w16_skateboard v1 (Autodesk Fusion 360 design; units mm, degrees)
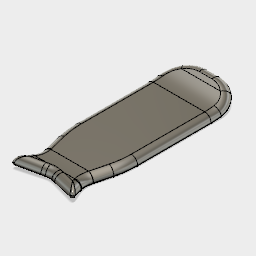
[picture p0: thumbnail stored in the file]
sketch "Sketch1" plane through (0, 0, 0) normal (1, 0, 0) x axis (0, 0, -1)
  line L1 (0, 0) -> (-50, 8.8163)
  line L2 (300, 0) -> (0, 0)
  line L3 (350, 18.1985) -> (300, 0)
  line L4 (-1.7498, -20) -> (-53.473, -10.8798)
  line L5 (303.5265, -20) -> (-1.7498, -20)
  line L6 (356.8404, -0.5953) -> (303.5265, -20)
  line L7 (-53.473, -10.8798) -> (-50, 8.8163)
  line L8 (356.8404, -0.5953) -> (350, 18.1985)
  point P4 (300, 0)
  point P5 (350, 18.1985)
  point P2 (-50, 8.8163)
  point P3 (0, 0)
  dimension "d1" angle L2 L3 = 160
  dimension "d2" distance P4 P5 = 50
  dimension "d3" distance P2 P3 = 50
  dimension "d4" angle L1 L2 = 170
  dimension "d5" distance P3 P4 = 300
  dimension "d6" = 20
extrude "Extrude1" new body sketch "Sketch1" along normal blind 150
sketch "Sketch2" plane through (0, 0, 0) normal (0, 1, 0) x axis (1, 0, 0)
  line L1 (0, 303.5265) -> (0, -1.7498)
  line L2 (0, 300) -> (0, 0)
  line L3 (150, 0) -> (0, 0)
  line L4 (20, 0) -> (0, 80)
  line L5 (150, -1.7498) -> (0, -1.7498)
  line L6 (150, 303.5265) -> (150, -1.7498)
  line L7 (130, -1.7498) -> (150, 76.527)
  line L8 (-75, 80) -> (0, 80)
  line L9 (-75, -100) -> (-75, 80)
  line L10 (225, -100) -> (-75, -100)
  line L11 (225, 74.8741) -> (225, -100)
  line L12 (150, 76.527) -> (225, 74.8741)
  line L13 (0, -50) -> (20, 0)
  line L14 (75, -30) -> (0, -50)
  line L15 (150, -50) -> (75, -30)
  line L16 (150, -50) -> (0, -50)
  line L17 (0, 0) -> (0, -50)
  line L18 (150, -50) -> (130, -1.7498)
  point P11 (150, -1.7498)
  point P12 (130, -1.7498)
  point P1 (0, 0)
  point P8 (20, 0)
  point P10 (150, -53.473)
  point P14 (150, 76.527)
  point P20 (75, -30)
  dimension "d9" distance P11 P12 = 20
  dimension "d10" distance P1 P8 = 20
  dimension "d11" distance P10 P14 = 130
  dimension "d19" distance P20 L16 = 20
  dimension "d20" distance P20 L17 = 75
extrude "Extrude4" cut sketch "Sketch2" profile of L1 L2 L5 L6 L8 L9 L10 L11 L12 L16 L17 L18 along normal blind 30
extrude "Extrude2" cut sketch "Sketch2" profile of L1 L2 L5 L6 L8 L9 L10 L11 L12 against normal blind 75
extrude "Extrude3" cut sketch "Sketch2" profile of L1 L2 L5 L6 L8 L9 L10 L11 L12 along normal blind 75
extrude "Extrude5" cut sketch "Sketch2" profile of L1 L2 L3 L4 L6 L7 against normal blind 50
sketch "Sketch5" plane through (0, 0, 0) normal (0, 1, 0) x axis (1, 0, 0)
  line L1 (0, -50) -> (20, 0)
  line L2 (20, 0) -> (0, -50)
  line L3 (0, -50) -> (0, 80)
extrude "Extrude6" cut sketch "Sketch2" profile of L1 L2 L3 L4 L5 L13 L17 against normal blind 50
extrude "Extrude7" cut sketch "Sketch2" profile of L1 L2 L3 L4 L5 L13 L17 along normal blind 4.601
sketch "Sketch6" plane through (0, 0, 0) normal (0, 1, 0) x axis (1, 0, 0)
  line L1 (130, -1.7498) -> (150, 76.527)
  line L2 (130, -1.7498) -> (150, 76.527)
  line L3 (150, 76.527) -> (150, -50)
extrude "Extrude8" cut sketch "Sketch2" profile of L1 L2 L3 L5 L6 L7 L8 L9 L10 L11 L12 L16 L17 L18 along normal blind 15
extrude "Extrude9" cut sketch "Sketch2" profile of L1 L2 L3 L5 L6 L7 L8 L9 L10 L11 L12 L16 L17 L18 against normal blind 160
fillet "Fillet1" radius 200
fillet "Fillet2" radius 150
fillet "Fillet3" radius 200
fillet "Fillet4" radius 50
fillet "Fillet5" radius 30
fillet "Fillet6" radius 5
fillet "Fillet7" radius 60
fillet "Fillet8" radius 15
fillet "Fillet9" radius 150
fillet "Fillet10" radius 4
